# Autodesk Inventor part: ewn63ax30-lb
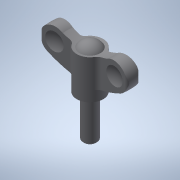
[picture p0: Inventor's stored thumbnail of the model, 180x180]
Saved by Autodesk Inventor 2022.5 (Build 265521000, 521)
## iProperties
Created: 2017-05
Part Number: ewn63ax30-lb
Material: 一般
Document SubType Name: Modeling
Designer: imaocorp
Density: 1 g/cm^3
Appearance: 既定
Author: imaocorp
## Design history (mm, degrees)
node "ewn63ax30-lb.x_t1"
node "ewn63ax30-lb"
node "Base1"
